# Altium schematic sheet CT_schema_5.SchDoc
size 258 x 163 mm
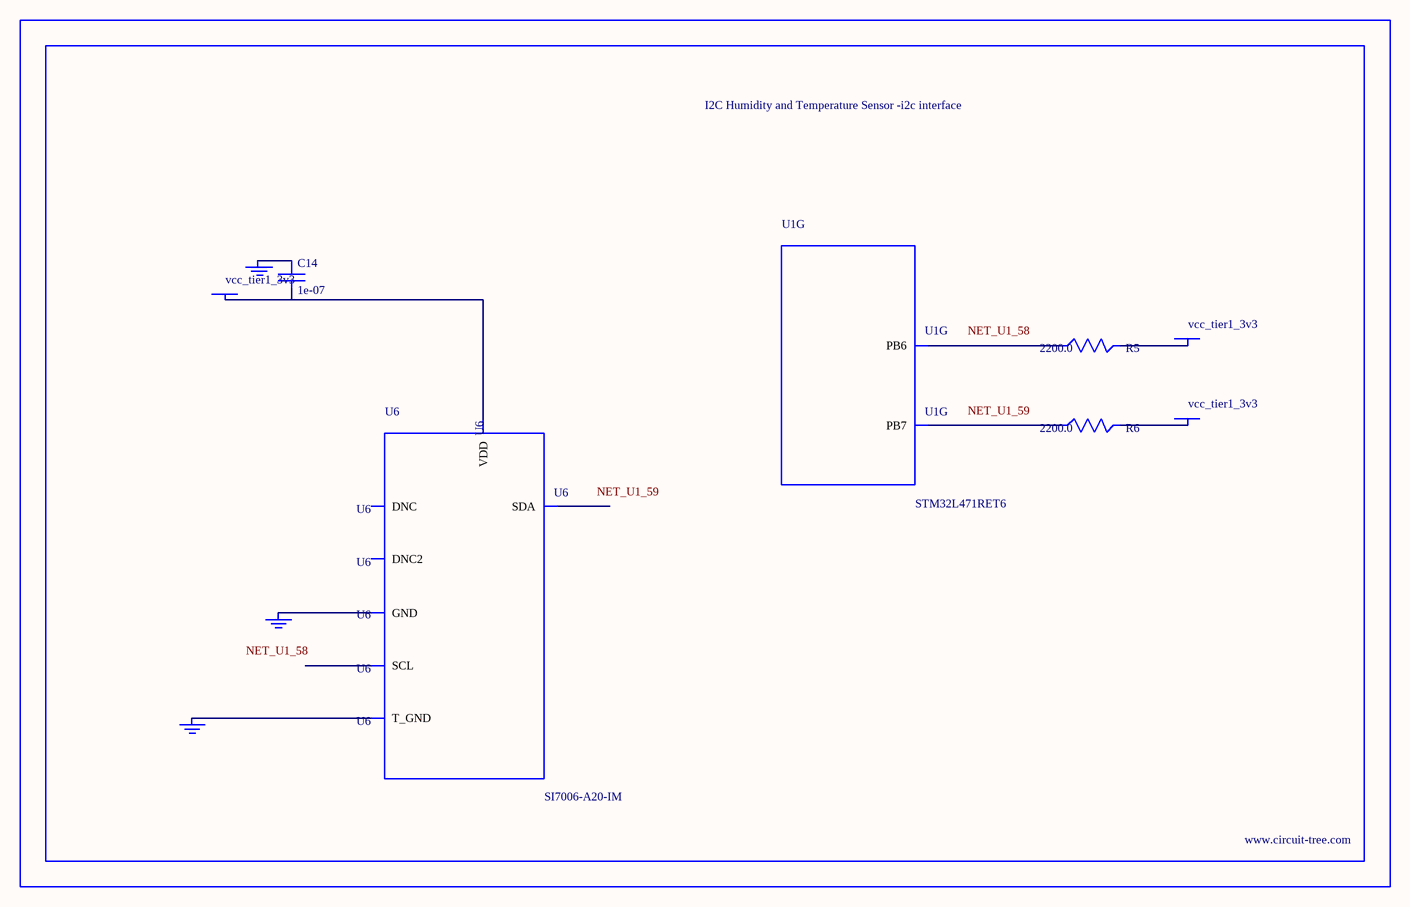
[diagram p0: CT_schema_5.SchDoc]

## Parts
BORDER4  (no value)
C14  1e-07  [C0402]
GND_INSTANCE_4_0  (no value)
GND_INSTANCE_4_1  (no value)
GND_INSTANCE_4_2  (no value)
POWER_INSTANCE_4_0  vcc_tier1_3v3
POWER_INSTANCE_4_1  vcc_tier1_3v3
POWER_INSTANCE_4_2  vcc_tier1_3v3
R5  2200.0  [R0603]
R6  2200.0  [R0603]
U1  STM32L471RET6  [LQFP64]  (part G of 8)
U6  SI7006-A20-IM  [DFN-6]

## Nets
NetC14_1: C14.1 GND_INSTANCE_4_0.0(GND)
NetC14_2: C14.2 POWER_INSTANCE_4_0.0(PWR) U6.5(VDD)
NetGND_INSTANCE_4_1_0: GND_INSTANCE_4_1.0(GND) U6.7(T_GND)
NetGND_INSTANCE_4_2_0: GND_INSTANCE_4_2.0(GND) U6.2(GND)
NetPOWER_INSTANCE_4_1_0: POWER_INSTANCE_4_1.0(PWR) R5.2
NetPOWER_INSTANCE_4_2_0: POWER_INSTANCE_4_2.0(PWR) R6.2
NetR5_1: R5.1 U1.58(PB6)
NetR6_1: R6.1 U1.59(PB7)

Not connected (* = marked no-connect by the designer): U6 1(SDA) 3(DNC) 4(DNC2) 6(SCL)

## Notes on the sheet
- Labels drawn without touching a wire or pin: NET_U1_58, NET_U1_59

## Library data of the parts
BORDER4 = BORDER_PAGE4
C14 = C0402C104K3RACTU
GND_INSTANCE_4_0-GND_INSTANCE_4_2 = GND
POWER_INSTANCE_4_0-POWER_INSTANCE_4_2 = PWR
R5 R6 = RC0603JR-072K2L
